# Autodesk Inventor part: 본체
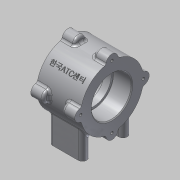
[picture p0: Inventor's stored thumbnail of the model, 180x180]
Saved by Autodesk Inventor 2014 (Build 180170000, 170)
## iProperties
Created: 2015-03
Part Number: 본체
Material: 알루미늄 6061
Document SubType Name: Modeling
Designer: MYHOME
Density: 2.71 g/cm^3
Appearance: 알루미늄 - 평지
Mass: 450.776 g
Surface Area: 332.745 cm^2
Volume: 166.338 cm^3
Author: MYHOME
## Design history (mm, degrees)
sketch "스케치2"
  geometry: C1 r 37 at (0, 0); 1 further point
  constraints: 1 centre point, 1 coincident
  dimensions: "d0" = 74 diameter of C1
extrude "돌출1" new body sketch "스케치2" stored distance "d1" = 52; taper "d2" = 0 deg
node "작업 평면1"
sketch "스케치3"
  geometry: L1 (-15, -24)-(15, -24); L2 (-15, -29)-(15, -29); L3 (15, -19)-(-15, -19); L4 (-15, 24)-(15, 24); L5 (-15, 19)-(15, 19); L6 (15, 29)-(-15, 29); A1 r 5 centre (-15, -24) between (-15, -19) and (-15, -29); A2 r 5 centre (15, -24) between (15, -29) and (15, -19); A3 r 5 centre (-15, 24) between (-15, 29) and (-15, 19); A4 r 5 centre (15, 24) between (15, 19) and (15, 29); 3 further points
  constraints: 16 end point, 8 point on circle, 8 tangent, 4 centre point, 3 parallel, 2 midpoint, 2 vertical alignment, 1 horizontal
  dimensions: "d4" = 10 distance between parallel lines of L3 L2; "d5" = 10 distance between parallel lines of L6 L5; "d6" = 40 dimension on A4 A3; "d7" = 40 dimension on A2 A1; "d8" = 48 distance of L4.start L1.start; "d9" = 24 distance of point (0, 0) point (0, -24)
extrude "돌출2" join sketch "스케치3" stored distance "d10" = 10; taper "d11" = 0 deg
sketch "스케치4"
  geometry: C1 r 7 at (0, 37); C2 r 7 at (-37, 0); C3 r 7 at (37, 0); C4 r 7 at (0, -37); A1 r 37 centre (0, 0) between (0, 37) and (-37, 0) reference
  constraints: 4 centre point, 4 point on circle, 2 horizontal alignment, 2 vertical alignment
  dimensions: "d12" = 14 diameter of C1; "d13" = 14 diameter of C2; "d14" = 14 diameter of C3; "d15" = 14 diameter of C4
extrude "돌출3" join sketch "스케치4" distance "d16" = 15; taper "d17" = 0 deg
sketch "스케치5"
  geometry: A1 r 7 centre (37, 0) between (36.338, -6.969) and (36.338, 6.969) reference; A2 r 7 centre (0, 37) between (6.969, 36.338) and (-6.969, 36.338) reference; A3 r 7 centre (-37, 0) between (-36.338, 6.969) and (-36.338, -6.969) reference; A4 r 7 centre (0, -37) between (-6.969, -36.338) and (6.969, -36.338) reference; 4 further points
  constraints: 4 coincident
hole "구멍1" sketch "스케치5" at (0, 37), (-37, 0), (37, 0), (0, -37) diameter "d18" = 3.242; stored, may be unused: countersink angle "d22" = 90 deg, drill point angle "d24" = 118 deg; dims "d19" = 8, "d20" = 4, "d21" = 2, "d23" = 11
sketch "스케치6"
  geometry: C1 r 23.5 at (0, 0); A1 r 37 centre (0, 0) between (-36.338, -6.969) and (-6.969, -36.338) reference
  constraints: 1 centre point, 1 coincident
  dimensions: "d25" = 47 diameter of C1
extrude "돌출4" cut sketch "스케치6" distance "d26" = 22; taper "d27" = 0 deg
sketch "스케치7"
  geometry: C1 r 23.5 at (0, 0); A1 r 37 centre (0, 0) between (-36.338, -6.969) and (-6.969, -36.338) reference
  constraints: 1 centre point, 1 coincident
  dimensions: "d28" = 47 diameter of C1
extrude "돌출5" cut sketch "스케치7" distance "d29" = 22; taper "d30" = 0 deg
sketch "스케치8"
  geometry: C1 r 23.5 at (0, 0) reference; C2 r 21 at (0, 0)
  constraints: 1 centre point, 1 coincident
  dimensions: "d31" = 42 diameter of C2
extrude "돌출6" cut sketch "스케치8" stored distance "d32" = 22; taper "d33" = 0 deg
chamfer "모따기1" distance "d34" = 1; stored, may be unused: second distance "d35" = 2, angle "d36" = 45 deg
fillet "모깎기1" dims "d37" = 0.3
sketch "스케치9"
  geometry: L1 (-15, 19)-(15, 19) reference; L2 (15, 29)-(-15, 29) reference; A1 r 5 centre (15, -24) between (15, -29) and (15, -19) reference; A2 r 5 centre (-15, -24) between (-15, -19) and (-15, -29) reference; A3 r 5 centre (15, 24) between (15, 19) and (15, 29) reference; A4 r 5 centre (-15, 24) between (-15, 29) and (-15, 19) reference; 5 further points
  constraints: 4 coincident
hole "구멍2" sketch "스케치9" at (-15, 24), (15, 24), (-15, -24), (15, -24) diameter "d38" = 4.134; stored, may be unused: countersink angle "d42" = 90 deg, drill point angle "d44" = 118 deg; dims "d39" = 6, "d40" = 4, "d41" = 2, "d43" = 8
sketch "스케치10"
  geometry: L1 (0, 0)-(-26.163, 26.163); L2 (0, 0)-(-37, 0); A1 r 37 centre (0, 0) between (-6.969, 36.338) and (-36.338, 6.969) reference; A2 r 37 centre (0, 0) between (-36.338, 6.969) and (-36.338, -6.969) reference; 2 further points
  constraints: 4 end point, 2 point on circle, 1 coincident
  dimensions: "d45" = 45 deg angle of L2 L1
node "작업 평면2"
sketch "스케치11"
  geometry: 3 further points
  constraints: 1 coincident, 1 other
feature "엠보싱1" sketch "스케치11" dims "d46" = 0.5, "d47" = 0
fillet "모깎기2" dims "d48" = 3
fillet "모깎기3" dims "d49" = 3
fillet "모깎기4" dims "d50" = 3
node "솔리드1"
mirror "대칭1"
node "투영된 루프1"
other parameters: "d3" = -56
